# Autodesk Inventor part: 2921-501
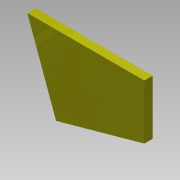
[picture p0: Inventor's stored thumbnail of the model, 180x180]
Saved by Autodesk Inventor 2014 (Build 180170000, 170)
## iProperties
Company: NHTSA/VRTTC
Created: 2011-11
Part Number: 2921-501
Material: Polyaryletherketone Resin
Document SubType Name: Modeling
Designer: Mike Vanvoorhis
Density: 1.32 g/cm^3
Project: CHILD SIDE IMPACT SLED
Description: Polyethylene Closed Cell Foam 2.2 PCF - SHT. 55 mm (2.2") x 773 mm (30.4") x 522 mm (20.6")
Mass: 19900 g
Surface Area: 7086.95 cm^2
Volume: 15075.7 cm^3
Appearance: Yellow
Author: Dave Walker
Title: IMPACTOR DOOR FOAM
Subject: Child Side Impact Sled
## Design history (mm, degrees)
sketch "Sketch3"
  geometry: L1 (-772.8, 0)-(0, 0); L2 (0, 0)-(0, -360.3); L3 (0, -360.3)-(-582.832, -521.934); L4 (-582.832, -521.934)-(-772.8, 0); 1 further point
  constraints: 8 end point, 1 coincident, 1 horizontal, 1 perpendicular
  dimensions: "d7" = 772.8 distance of L1.start L1.end; "d9" = 360.3 distance of L1.end L2.end; "d10" = 105.5 deg angle of L3 L2; "d14" = 604.82909 distance of L2.end L3.end (derived); "d16" = 70 deg angle of L1 L4; "d17" = 555.43007 distance of L3.end L1.start (derived)
extrude "Extrusion2" new body sketch "Sketch3" distance "d12" = 55; taper "d13" = 0 deg
body "Solid3"
